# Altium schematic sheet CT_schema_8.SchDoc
size 277 x 170 mm
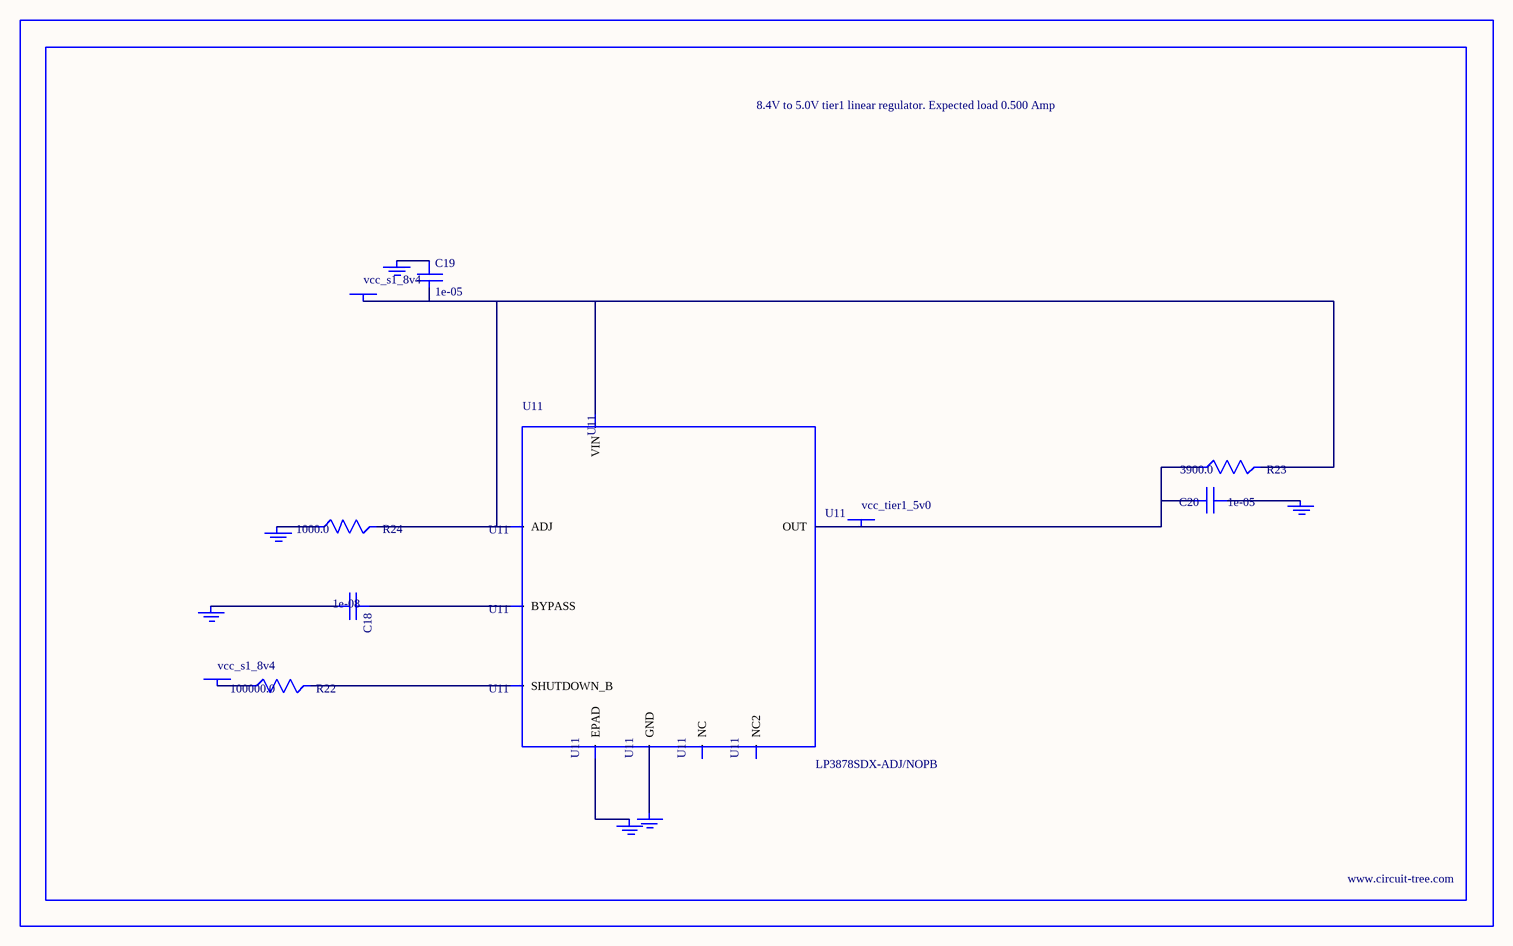
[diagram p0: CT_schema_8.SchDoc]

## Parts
BORDER7  (no value)
C18  1e-08  [C0402]
C19  1e-05  [C1206]
C20  1e-05  [C1210]
GND_INSTANCE_7_0  (no value)
GND_INSTANCE_7_1  (no value)
GND_INSTANCE_7_2  (no value)
GND_INSTANCE_7_3  (no value)
GND_INSTANCE_7_4  (no value)
GND_INSTANCE_7_5  (no value)
POWER_INSTANCE_7_0  vcc_s1_8v4
POWER_INSTANCE_7_1  vcc_s1_8v4
POWER_INSTANCE_7_2  vcc_tier1_5v0
R22  100000.0  [R0603]
R23  3900.0  [R0603]
R24  1000.0  [R0603]
U11  LP3878SDX-ADJ/NOPB  [WSON-8]

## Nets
NetC18_1: C18.1 U11.1(BYPASS)
NetC18_2: C18.2 GND_INSTANCE_7_0.0(GND)
NetC19_1: C19.1 GND_INSTANCE_7_1.0(GND)
NetC19_2: C19.2 POWER_INSTANCE_7_0.0(PWR) R23.2 R24.2 U11.4(VIN) U11.6(ADJ)
NetC20_1: C20.1 GND_INSTANCE_7_2.0(GND)
NetC20_2: C20.2 POWER_INSTANCE_7_2.0(PWR) R23.1 U11.5(OUT)
NetGND_INSTANCE_7_3_0: GND_INSTANCE_7_3.0(GND) R24.1
NetGND_INSTANCE_7_4_0: GND_INSTANCE_7_4.0(GND) U11.PAD(EPAD)
NetGND_INSTANCE_7_5_0: GND_INSTANCE_7_5.0(GND) U11.3(GND)
NetPOWER_INSTANCE_7_1_0: POWER_INSTANCE_7_1.0(PWR) R22.1
NetR22_2: R22.2 U11.8(SHUTDOWN_B)

Not connected (* = marked no-connect by the designer): U11 2(NC) 7(NC2)

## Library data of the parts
BORDER7 = BORDER_PAGE7
C18 = C0402C103K3RAC
C19 = C1206C106K3RACTU
C20 = GRM32DR61E106MA12L
GND_INSTANCE_7_0-GND_INSTANCE_7_5 = GND
POWER_INSTANCE_7_0-POWER_INSTANCE_7_2 = PWR
R22 = RC0603JR-07100KL
R23 = RC0603JR-073K9L
R24 = RC0603JR-071KL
